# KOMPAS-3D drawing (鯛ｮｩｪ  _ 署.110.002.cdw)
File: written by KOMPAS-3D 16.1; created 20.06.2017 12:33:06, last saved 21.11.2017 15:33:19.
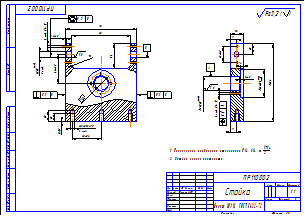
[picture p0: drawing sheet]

Sheet 1: A3, landscape

Title block, sheet 1: name: Стойка; designation: ПР.110.002; material: Полоса 30Х13  ГОСТ 5632-72; scale: 1:1; sheets: 1; sheet format: A3; stored path: C:\Users\Сергей\Desktop\Каретка _ ПР.010.017.cdw; drawn by: Сигачев СИ

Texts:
  Сергей
  Неуказанные предельные отклонения H14, h14,    IT14 2 .
  Острые кромки притупить.
  Ra3,2
  Ra3,2 ( )
  CONTINUOUS_RGB_0_0_0_THICK_0.18
  CONTINUOUS_RGB_0_0_255_THICK_0.18
  CONTINUOUS_RGB_0_255_0_THICK_0.18
  СONTINUOUS_RGB_0_255_0_THICK_-0.03
  CONTINUOUS_RGB_0_0_0_THICK_-0.03
Dimensions and other numbers on the sheet: 28; -7Н; 4 отв.; 3; 20; 1,6; 0,1; 6; 3 отв.; 40±0,2; 1; 12; 15; 5; 34; 82; 98; 0,5; 8; 2 отв.; 9; 18; 22±0,1; 4; 38; 108; 1:1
